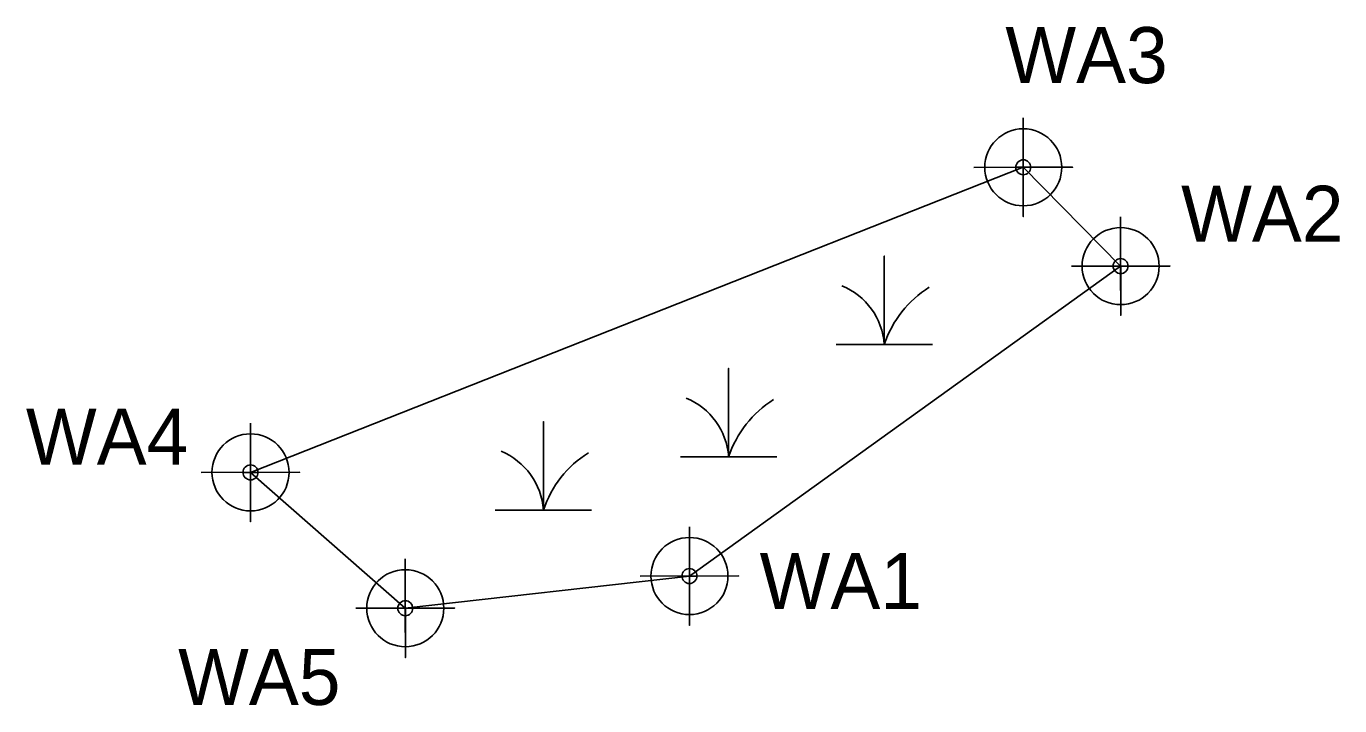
# Model space of a CAD drawing. Extents: x 1769158.9 to 1769246.8, y 1000519.9 to 1000565.4.
import ezdxf

# ---------------------------------------------------------------- set-up
doc = ezdxf.new("R2010")
doc.units = 0
for name, color, linetype in [('Default', 7, 'Continuous'), ('E_ENV_SWAMP_SYMBOL_PT', 7, 'Continuous'), ('E_ENV_WETLAND_BOUNDARY', 7, 'Continuous'), ('Exist Environmental Wetland Boundary Cogo Number', 7, 'Continuous'), ('Exist Hydro Stream or Body of Water Cogo Point CELL', 7, 'Continuous')]:
    doc.layers.add(name, color=color, linetype=linetype)

# ---------------------------------------------------------------- blocks, each defined once
blk = doc.blocks.new('SurveyPointCell')
at = {"layer": 'Default'}
for p, q in [((-0.5, 0), (0.5, 0)), ((0, -0.5), (0, 0.5))]:
    blk.add_line(p, q, dxfattribs=at)
blk.add_circle((0, 0), 0.5, dxfattribs=at)

msp = doc.modelspace()

# ---------------------------------------------------------------- linework, layer by layer
at = {"layer": 'E_ENV_SWAMP_SYMBOL_PT'}
for p, q in [((1769216.318, 1000546.757), (1769216.318, 1000546.757)), ((1769205.901, 1000539.237), (1769205.901, 1000539.237)), ((1769193.506, 1000535.675), (1769193.506, 1000535.675))]:
    msp.add_line(p, q, dxfattribs=at)
for points in [[(1769213.093, 1000544.082), (1769216.318, 1000544.082), (1769216.318, 1000550), (1769216.318, 1000544.082), (1769219.544, 1000544.082)], [(1769202.676, 1000536.563), (1769205.901, 1000536.563), (1769205.901, 1000542.48), (1769205.901, 1000536.563), (1769209.127, 1000536.563)], [(1769190.281, 1000533.001), (1769193.507, 1000533.001), (1769193.507, 1000538.918), (1769193.507, 1000533.001), (1769196.732, 1000533.001)]]:
    msp.add_lwpolyline(points, dxfattribs=at)
for centre, radius, start, end in [((1769211.718, 1000543.749), 4.612, 4.14034, 67.53497), ((1769223.159, 1000541.81), 7.208, 122.12745, 161.62219), ((1769201.302, 1000536.23), 4.612, 4.14034, 67.53497), ((1769212.742, 1000534.29), 7.208, 122.12745, 161.62219), ((1769188.907, 1000532.668), 4.612, 4.14034, 67.53497), ((1769200.347, 1000530.728), 7.208, 122.12745, 161.62219)]:
    msp.add_arc(centre, radius, start, end, dxfattribs=at)
at = {"layer": 'E_ENV_WETLAND_BOUNDARY'}
for p, q in [((1769173.904, 1000535.52), (1769225.615, 1000555.938)), ((1769225.615, 1000555.938), (1769232.133, 1000549.323)), ((1769232.133, 1000549.323), (1769203.278, 1000528.583)), ((1769184.262, 1000526.431), (1769173.904, 1000535.52)), ((1769203.278, 1000528.583), (1769184.262, 1000526.431))]:
    msp.add_line(p, q, dxfattribs=at)
at = {"layer": 'Exist Hydro Stream or Body of Water Cogo Point CELL'}
for points in [[(1769225.61, 1000559.238), (1769225.62, 1000552.638), (1769225.615, 1000555.938), (1769228.915, 1000555.943), (1769222.315, 1000555.933)], [(1769232.128, 1000552.623), (1769232.138, 1000546.023), (1769232.133, 1000549.323), (1769235.433, 1000549.328), (1769228.833, 1000549.318)], [(1769173.899, 1000538.82), (1769173.909, 1000532.22), (1769173.904, 1000535.52), (1769177.204, 1000535.525), (1769170.604, 1000535.515)], [(1769203.273, 1000531.883), (1769203.283, 1000525.283), (1769203.278, 1000528.583), (1769206.578, 1000528.588), (1769199.978, 1000528.578)], [(1769184.257, 1000529.731), (1769184.267, 1000523.131), (1769184.262, 1000526.431), (1769187.562, 1000526.436), (1769180.962, 1000526.426)]]:
    msp.add_lwpolyline(points, dxfattribs=at)
for centre in [(1769225.615, 1000555.938), (1769232.133, 1000549.323), (1769173.904, 1000535.52), (1769203.278, 1000528.583), (1769184.262, 1000526.431)]:
    msp.add_circle(centre, 2.578, dxfattribs=at)

# ---------------------------------------------------------------- block references
at = {"layer": 'Default'}
for p in [(1769225.615, 1000555.938), (1769232.133, 1000549.323), (1769173.904, 1000535.52), (1769203.278, 1000528.583), (1769184.262, 1000526.431)]:
    msp.add_blockref('SurveyPointCell', p, dxfattribs=at)

# ---------------------------------------------------------------- texts
at = {"layer": 'Exist Environmental Wetland Boundary Cogo Number'}
for s, p in [('WA3', (1769224.419, 1000561.569)), ('WA2', (1769236.179, 1000550.951)), ('WA4', (1769158.876, 1000536.028)), ('WA1', (1769207.976, 1000526.37)), ('WA5', (1769169.058, 1000519.957))]:
    msp.add_text(s, height=3.75, dxfattribs=at).set_placement(p)

doc.saveas('drawing.dxf')
